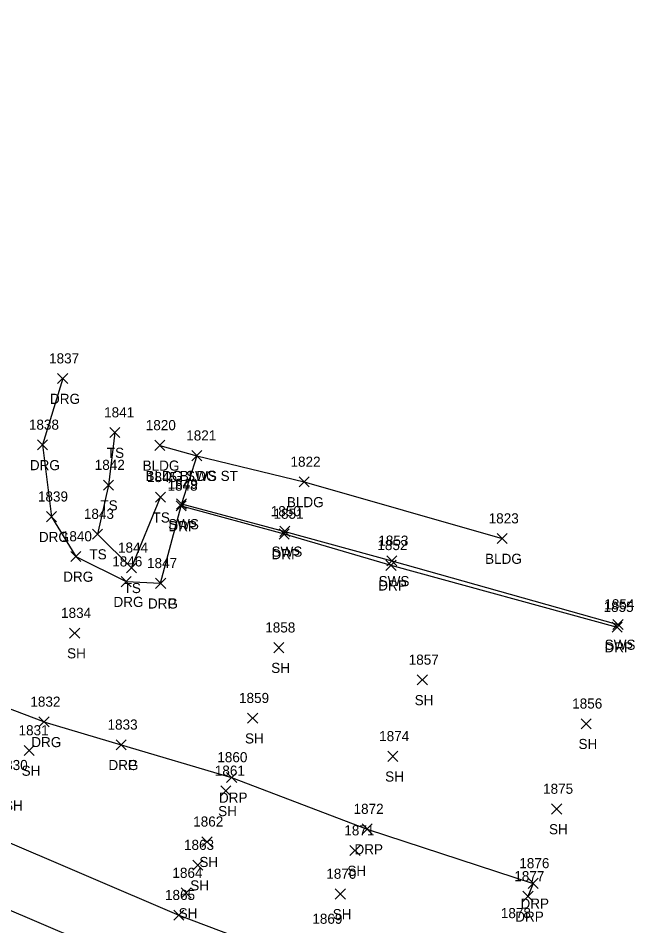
# Model space of a CAD drawing. Extents: x 1586965 to 1590952, y 716317 to 720029.
# Drawn here: x 1588139.1 to 1588261.1, y 719679.3 to 719858.7 of the extents above; entities that cross this region are included whole.
import ezdxf

# ---------------------------------------------------------------- set-up
doc = ezdxf.new("R2010")
doc.units = 0
for name, color, linetype in [('L_A', 7, 'Continuous'), ('L_I', 7, 'Continuous'), ('L_TIC', 7, 'Continuous'), ('LBC', 7, 'Continuous'), ('LELB', 7, 'Continuous'), ('P_I', 7, 'Continuous'), ('P_TIC', 7, 'Continuous'), ('PET', 7, 'Continuous'), ('PRC', 7, 'Continuous'), ('R_A', 7, 'Continuous'), ('R_I', 7, 'Continuous'), ('R_TIC', 7, 'Continuous'), ('RDG', 7, 'Continuous'), ('RDP', 7, 'Continuous'), ('RSW', 7, 'Continuous')]:
    doc.layers.add(name, color=color, linetype=linetype)

msp = doc.modelspace()

# ---------------------------------------------------------------- linework, layer by layer
at = {"layer": 'L_TIC'}
for points in [[(1588157.22, 719775.81), (1588159.22, 719777.81)], [(1588159.22, 719775.81), (1588157.22, 719777.81)], [(1588166.11, 719773.28), (1588168.11, 719775.28)], [(1588168.11, 719773.28), (1588166.11, 719775.28)], [(1588173.45, 719771.24), (1588175.45, 719773.24)], [(1588175.45, 719771.24), (1588173.45, 719773.24)], [(1588155.94, 719765.42), (1588157.94, 719767.42)], [(1588157.94, 719765.42), (1588155.94, 719767.42)], [(1588194.64, 719766.05), (1588196.64, 719768.05)], [(1588196.64, 719766.05), (1588194.64, 719768.05)], [(1588166.26, 719763.02), (1588168.26, 719765.02)], [(1588168.26, 719763.02), (1588166.26, 719765.02)], [(1588153.78, 719755.74), (1588155.78, 719757.74)], [(1588155.78, 719755.74), (1588153.78, 719757.74)], [(1588233.83, 719754.85), (1588235.83, 719756.85)], [(1588235.83, 719754.85), (1588233.83, 719756.85)], [(1588160.53, 719749.07), (1588162.53, 719751.07)], [(1588162.53, 719749.07), (1588160.53, 719751.07)], [(1588149.28, 719736.16), (1588151.28, 719738.16)], [(1588151.28, 719736.16), (1588149.28, 719738.16)], [(1588189.66, 719733.28), (1588191.66, 719735.28)], [(1588191.66, 719733.28), (1588189.66, 719735.28)], [(1588218.02, 719726.91), (1588220.02, 719728.91)], [(1588220.02, 719726.91), (1588218.02, 719728.91)], [(1588184.47, 719719.34), (1588186.47, 719721.34)], [(1588186.47, 719719.34), (1588184.47, 719721.34)], [(1588250.41, 719718.24), (1588252.41, 719720.24)], [(1588252.41, 719718.24), (1588250.41, 719720.24)], [(1588140.29, 719712.95), (1588142.29, 719714.95)], [(1588142.29, 719712.95), (1588140.29, 719714.95)], [(1588212.18, 719711.8), (1588214.18, 719713.8)], [(1588214.18, 719711.8), (1588212.18, 719713.8)], [(1588179.15, 719704.97), (1588181.15, 719706.97)], [(1588181.15, 719704.97), (1588179.15, 719706.97)], [(1588244.6, 719701.39), (1588246.6, 719703.39)], [(1588246.6, 719701.39), (1588244.6, 719703.39)], [(1588175.45, 719694.91), (1588177.45, 719696.91)], [(1588177.45, 719694.91), (1588175.45, 719696.91)], [(1588204.71, 719693.17), (1588206.71, 719695.17)], [(1588206.71, 719693.17), (1588204.71, 719695.17)], [(1588173.63, 719690.29), (1588175.63, 719692.29)], [(1588175.63, 719690.29), (1588173.63, 719692.29)], [(1588171.34, 719684.77), (1588173.34, 719686.77)], [(1588173.34, 719684.77), (1588171.34, 719686.77)], [(1588201.81, 719684.59), (1588203.81, 719686.59)], [(1588203.81, 719684.59), (1588201.81, 719686.59)]]:
    msp.add_lwpolyline(points, dxfattribs=at)
at = {"layer": 'LBC'}
msp.add_lwpolyline([(1588167.11, 719774.28), (1588174.45, 719772.24), (1588195.64, 719767.05), (1588234.83, 719755.85)], dxfattribs=at)
at = {"layer": 'LELB'}
msp.add_lwpolyline([(1588158.22, 719776.81), (1588156.94, 719766.42), (1588154.78, 719756.74), (1588161.53, 719750.07), (1588167.26, 719764.02)], dxfattribs=at)
msp.add_lwpolyline([(1588158.22, 719776.81), (1588156.94, 719766.42), (1588154.78, 719756.74), (1588161.53, 719750.07), (1588167.26, 719764.02)], dxfattribs=at)
at = {"layer": 'P_TIC'}
for points in [[(1588169.87, 719680.39), (1588171.87, 719682.39)], [(1588171.87, 719680.39), (1588169.87, 719682.39)]]:
    msp.add_lwpolyline(points, dxfattribs=at)
at = {"layer": 'PET'}
msp.add_lwpolyline([(1587795.98, 719858.74), (1587820.3, 719853.13), (1587857.37, 719841.42), (1587877.69, 719833.83), (1587907.04, 719819.84), (1587939.32, 719802.03), (1587973.69, 719783.16), (1588008.21, 719763.34), (1588019.61, 719757.58), (1588045.18, 719744.38), (1588072.84, 719731.02), (1588081.8, 719723.85), (1588104.43, 719712.22), (1588133.68, 719697.26), (1588170.87, 719681.39), (1588198.42, 719670.99), (1588228.28, 719659.25)], dxfattribs=at)
at = {"layer": 'PRC'}
msp.add_lwpolyline([(1587770.57, 719846.88), (1587822.37, 719838.71), (1587852.49, 719828.95), (1587873.58, 719820.04), (1587901.35, 719807.55), (1587933.49, 719790.19), (1587967.95, 719771.53), (1588001.84, 719751.71), (1588038.72, 719731.7), (1588068.79, 719715.56), (1588099.02, 719700.65), (1588127.2, 719686.75), (1588167.73, 719669.46), (1588194.58, 719658.84), (1588224.51, 719647.27)], dxfattribs=at)
msp.add_lwpolyline([(1587770.57, 719846.88), (1587822.37, 719838.71), (1587852.49, 719828.95), (1587873.58, 719820.04), (1587901.35, 719807.55), (1587933.49, 719790.19), (1587967.95, 719771.53), (1588001.84, 719751.71), (1588038.72, 719731.7), (1588068.79, 719715.56), (1588099.02, 719700.65), (1588127.2, 719686.75), (1588167.73, 719669.46), (1588194.58, 719658.84), (1588224.51, 719647.27)], dxfattribs=at)
at = {"layer": 'R_TIC'}
for points in [[(1588146.9, 719786.48), (1588148.9, 719788.48)], [(1588148.9, 719786.48), (1588146.9, 719788.48)], [(1588142.91, 719773.37), (1588144.91, 719775.37)], [(1588144.91, 719773.37), (1588142.91, 719775.37)], [(1588173.45, 719771.24), (1588175.45, 719773.24)], [(1588175.45, 719771.24), (1588173.45, 719773.24)], [(1588170.38, 719761.69), (1588172.38, 719763.69)], [(1588172.38, 719761.69), (1588170.38, 719763.69)], [(1588170.33, 719761.31), (1588172.33, 719763.31)], [(1588172.33, 719761.31), (1588170.33, 719763.31)], [(1588144.7, 719759.17), (1588146.7, 719761.17)], [(1588146.7, 719759.17), (1588144.7, 719761.17)], [(1588190.83, 719756.27), (1588192.83, 719758.27)], [(1588192.83, 719756.27), (1588190.83, 719758.27)], [(1588190.72, 719755.76), (1588192.72, 719757.76)], [(1588192.72, 719755.76), (1588190.72, 719757.76)], [(1588149.51, 719751.31), (1588151.51, 719753.31)], [(1588151.51, 719751.31), (1588149.51, 719753.31)], [(1588211.82, 719749.57), (1588213.82, 719751.57)], [(1588213.82, 719749.57), (1588211.82, 719751.57)], [(1588212.01, 719750.44), (1588214.01, 719752.44)], [(1588214.01, 719750.44), (1588212.01, 719752.44)], [(1588159.45, 719746.33), (1588161.45, 719748.33)], [(1588161.45, 719746.33), (1588159.45, 719748.33)], [(1588166.27, 719746.01), (1588168.27, 719748.01)], [(1588168.27, 719746.01), (1588166.27, 719748.01)], [(1588166.27, 719746.01), (1588168.27, 719748.01)], [(1588168.27, 719746.01), (1588166.27, 719748.01)], [(1588256.56, 719737.35), (1588258.56, 719739.35)], [(1588258.56, 719737.35), (1588256.56, 719739.35)], [(1588256.71, 719737.86), (1588258.71, 719739.86)], [(1588258.71, 719737.86), (1588256.71, 719739.86)], [(1588143.2, 719718.61), (1588145.2, 719720.61)], [(1588145.2, 719718.61), (1588143.2, 719720.61)], [(1588158.46, 719714.08), (1588160.46, 719716.08)], [(1588160.46, 719714.08), (1588158.46, 719716.08)], [(1588158.46, 719714.08), (1588160.46, 719716.08)], [(1588160.46, 719714.08), (1588158.46, 719716.08)], [(1588180.31, 719707.63), (1588182.31, 719709.63)], [(1588182.31, 719707.63), (1588180.31, 719709.63)], [(1588207.11, 719697.42), (1588209.11, 719699.42)], [(1588209.11, 719697.42), (1588207.11, 719699.42)], [(1588239.95, 719686.68), (1588241.95, 719688.68)], [(1588241.95, 719686.68), (1588239.95, 719688.68)], [(1588238.91, 719684.11), (1588240.91, 719686.11)], [(1588240.91, 719684.11), (1588238.91, 719686.11)]]:
    msp.add_lwpolyline(points, dxfattribs=at)
at = {"layer": 'RDG'}
for points in [[(1588147.9, 719787.48), (1588143.91, 719774.37), (1588145.7, 719760.17), (1588150.51, 719752.31), (1588160.45, 719747.33), (1588167.27, 719747.01)], [(1588144.2, 719719.61), (1588119.75, 719728.86)], [(1588144.2, 719719.61), (1588159.46, 719715.08)]]:
    msp.add_lwpolyline(points, dxfattribs=at)
at = {"layer": 'RDP'}
for points in [[(1588167.27, 719747.01), (1588171.33, 719762.31), (1588191.72, 719756.76), (1588212.82, 719750.57), (1588257.56, 719738.35)], [(1588159.46, 719715.08), (1588181.31, 719708.63), (1588208.11, 719698.42), (1588240.95, 719687.68), (1588239.91, 719685.11)]]:
    msp.add_lwpolyline(points, dxfattribs=at)
at = {"layer": 'RSW'}
msp.add_lwpolyline([(1588174.45, 719772.24), (1588171.38, 719762.69), (1588191.83, 719757.27), (1588213.01, 719751.44), (1588257.71, 719738.86)], dxfattribs=at)

# ---------------------------------------------------------------- texts
at = {"layer": 'L_A'}
for s, p in [('TS', (1588156.63, 719771.81)), ('BLDG', (1588163.7, 719769.28)), ('BLDG', (1588171.04, 719767.24)), ('TS', (1588155.35, 719761.42)), ('BLDG', (1588192.23, 719762.05)), ('TS', (1588165.67, 719759.02)), ('TS', (1588153.19, 719751.74)), ('BLDG', (1588231.43, 719750.85)), ('TS', (1588159.94, 719745.07)), ('SH', (1588148.77, 719732.16)), ('SH', (1588189.14, 719729.28)), ('SH', (1588217.51, 719722.91)), ('SH', (1588183.96, 719715.34)), ('SH', (1588249.9, 719714.24)), ('SH', (1588139.78, 719708.95)), ('SH', (1588211.67, 719707.8)), ('SH', (1588136.3, 719702.08)), ('SH', (1588178.64, 719700.97)), ('SH', (1588244.08, 719697.39)), ('SH', (1588174.93, 719690.91)), ('SH', (1588204.2, 719689.17)), ('SH', (1588173.12, 719686.29)), ('SH', (1588170.83, 719680.77)), ('SH', (1588201.3, 719680.59))]:
    msp.add_text(s, height=2, dxfattribs=at).set_placement(p)
at = {"layer": 'L_I'}
for s, p in [('1841', (1588156.09, 719779.81)), ('1820', (1588164.33, 719777.28)), ('1821', (1588172.33, 719775.24)), ('1842', (1588154.24, 719769.42)), ('1822', (1588192.95, 719770.05)), ('1845', (1588164.57, 719767.02)), ('1843', (1588152.09, 719759.74)), ('1823', (1588232.14, 719758.85)), ('1844', (1588158.84, 719753.07)), ('1834', (1588147.58, 719740.16)), ('1858', (1588187.96, 719737.28)), ('1857', (1588216.33, 719730.91)), ('1859', (1588182.77, 719723.34)), ('1856', (1588248.66, 719722.24)), ('1831', (1588139.17, 719716.95)), ('1874', (1588210.48, 719715.8)), ('1830', (1588135.03, 719710.08)), ('1861', (1588177.98, 719708.97)), ('1875', (1588242.9, 719705.39)), ('1862', (1588173.71, 719698.91)), ('1871', (1588203.59, 719697.17)), ('1863', (1588171.89, 719694.29)), ('1864', (1588169.6, 719688.77)), ('1870', (1588200.03, 719688.59)), ('1878', (1588234.55, 719680.81)), ('1869', (1588197.27, 719679.69))]:
    msp.add_text(s, height=2, dxfattribs=at).set_placement(p)
at = {"layer": 'P_I'}
msp.add_text('1865', height=2, dxfattribs=at).set_placement((1588168.13, 719684.39))
at = {"layer": 'R_A'}
for s, p in [('DRG', (1588145.39, 719782.48)), ('DRG', (1588141.4, 719769.37)), ('BLDG SWS ST', (1588164.27, 719767.24)), ('SWS', (1588168.75, 719757.69)), ('DRP', (1588168.81, 719757.31)), ('DRG', (1588143.19, 719755.17)), ('SWS', (1588189.2, 719752.27)), ('DRP', (1588189.21, 719751.76)), ('DRG', (1588148, 719747.31)), ('SWS', (1588210.38, 719746.44)), ('DRP', (1588210.31, 719745.57)), ('DRG', (1588157.94, 719742.33)), ('DRG', (1588164.76, 719742.01)), ('DRP', (1588164.76, 719742.01)), ('SWS', (1588255.08, 719733.86)), ('DRP', (1588255.05, 719733.35)), ('DRG', (1588141.69, 719714.61)), ('DRG', (1588156.95, 719710.08)), ('DRP', (1588156.95, 719710.08)), ('DRP', (1588178.8, 719703.63)), ('DRP', (1588205.6, 719693.42)), ('DRP', (1588238.43, 719682.68)), ('DRP', (1588237.4, 719680.11))]:
    msp.add_text(s, height=2, dxfattribs=at).set_placement(p)
at = {"layer": 'R_I'}
for s, p in [('1837', (1588145.21, 719790.48)), ('1838', (1588141.22, 719777.37)), ('1821', (1588172.33, 719775.24)), ('1848', (1588168.63, 719765.31)), ('1849', (1588168.68, 719765.69)), ('1839', (1588143, 719763.17)), ('1850', (1588189.05, 719760.27)), ('1851', (1588189.59, 719759.76)), ('1840', (1588147.73, 719755.31)), ('1853', (1588210.32, 719754.44)), ('1852', (1588210.13, 719753.57)), ('1846', (1588157.7, 719750.33)), ('1847', (1588164.58, 719750.01)), ('1847', (1588164.58, 719750.01)), ('1854', (1588255.02, 719741.86)), ('1855', (1588254.86, 719741.35)), ('1832', (1588141.51, 719722.61)), ('1833', (1588156.77, 719718.08)), ('1833', (1588156.77, 719718.08)), ('1860', (1588178.48, 719711.63)), ('1872', (1588205.42, 719701.42)), ('1876', (1588238.2, 719690.68)), ('1877', (1588237.21, 719688.11))]:
    msp.add_text(s, height=2, dxfattribs=at).set_placement(p)

doc.saveas('drawing.dxf')
